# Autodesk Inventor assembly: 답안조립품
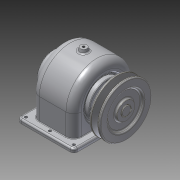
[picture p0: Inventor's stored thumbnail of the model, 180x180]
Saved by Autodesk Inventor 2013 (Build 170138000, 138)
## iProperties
Created: 2015-09
Part Number: 답안조립품
Document SubType Name: Assembly
Designer: Administrator
Author: Administrator
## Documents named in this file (13)
- C:\Documents and Settings\Administrator\바탕 화면\450908v1019\답안조립품.iam
- C:\Documents and Settings\Administrator\바탕 화면\450908v1019\1-본체.ipt
- C:\Documents and Settings\Administrator\바탕 화면\450908v1019\베어링 6203.ipt
- C:\Documents and Settings\Administrator\바탕 화면\450908v1019\축.ipt
- C:\Documents and Settings\Administrator\바탕 화면\450908v1019\키 - 6 x 6 x 22.ipt
- C:\Documents and Settings\Administrator\바탕 화면\450908v1019\스퍼기어.ipt
- C:\Documents and Settings\Administrator\바탕 화면\450908v1019\뒤커버.ipt
- C:\Documents and Settings\Administrator\바탕 화면\450908v1019\볼트 M3 x 8.ipt
- C:\Documents and Settings\Administrator\바탕 화면\450908v1019\앞커버.ipt
- C:\Documents and Settings\Administrator\바탕 화면\450908v1019\볼트 M3 x 10.ipt
- C:\Documents and Settings\Administrator\바탕 화면\450908v1019\V-벨트풀리.ipt
- C:\Documents and Settings\Administrator\바탕 화면\450908v1019\오일 실 17 32 8.ipt
- C:\Documents and Settings\Administrator\바탕 화면\450908v1019\멈춤나사 - M4x10.ipt
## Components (10 placed, 4 different names)
1. 1-본체:1
2. V-벨트풀리:1 — 각도:4
3. ISO 4762 M3 x 8:1
4. ISO 4762 M3 x 8:2
5. ISO 4762 M3 x 8:3
6. ISO 4762 M3 x 8:4
7. ISO 4762 M3 x 10:1
8. ISO 4762 M3 x 10:2
9. ISO 4762 M3 x 10:3
10. ISO 4762 M3 x 10:4
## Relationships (1: Angle 1)
- 각도:4 [Angle]: V-벨트풀리:1
